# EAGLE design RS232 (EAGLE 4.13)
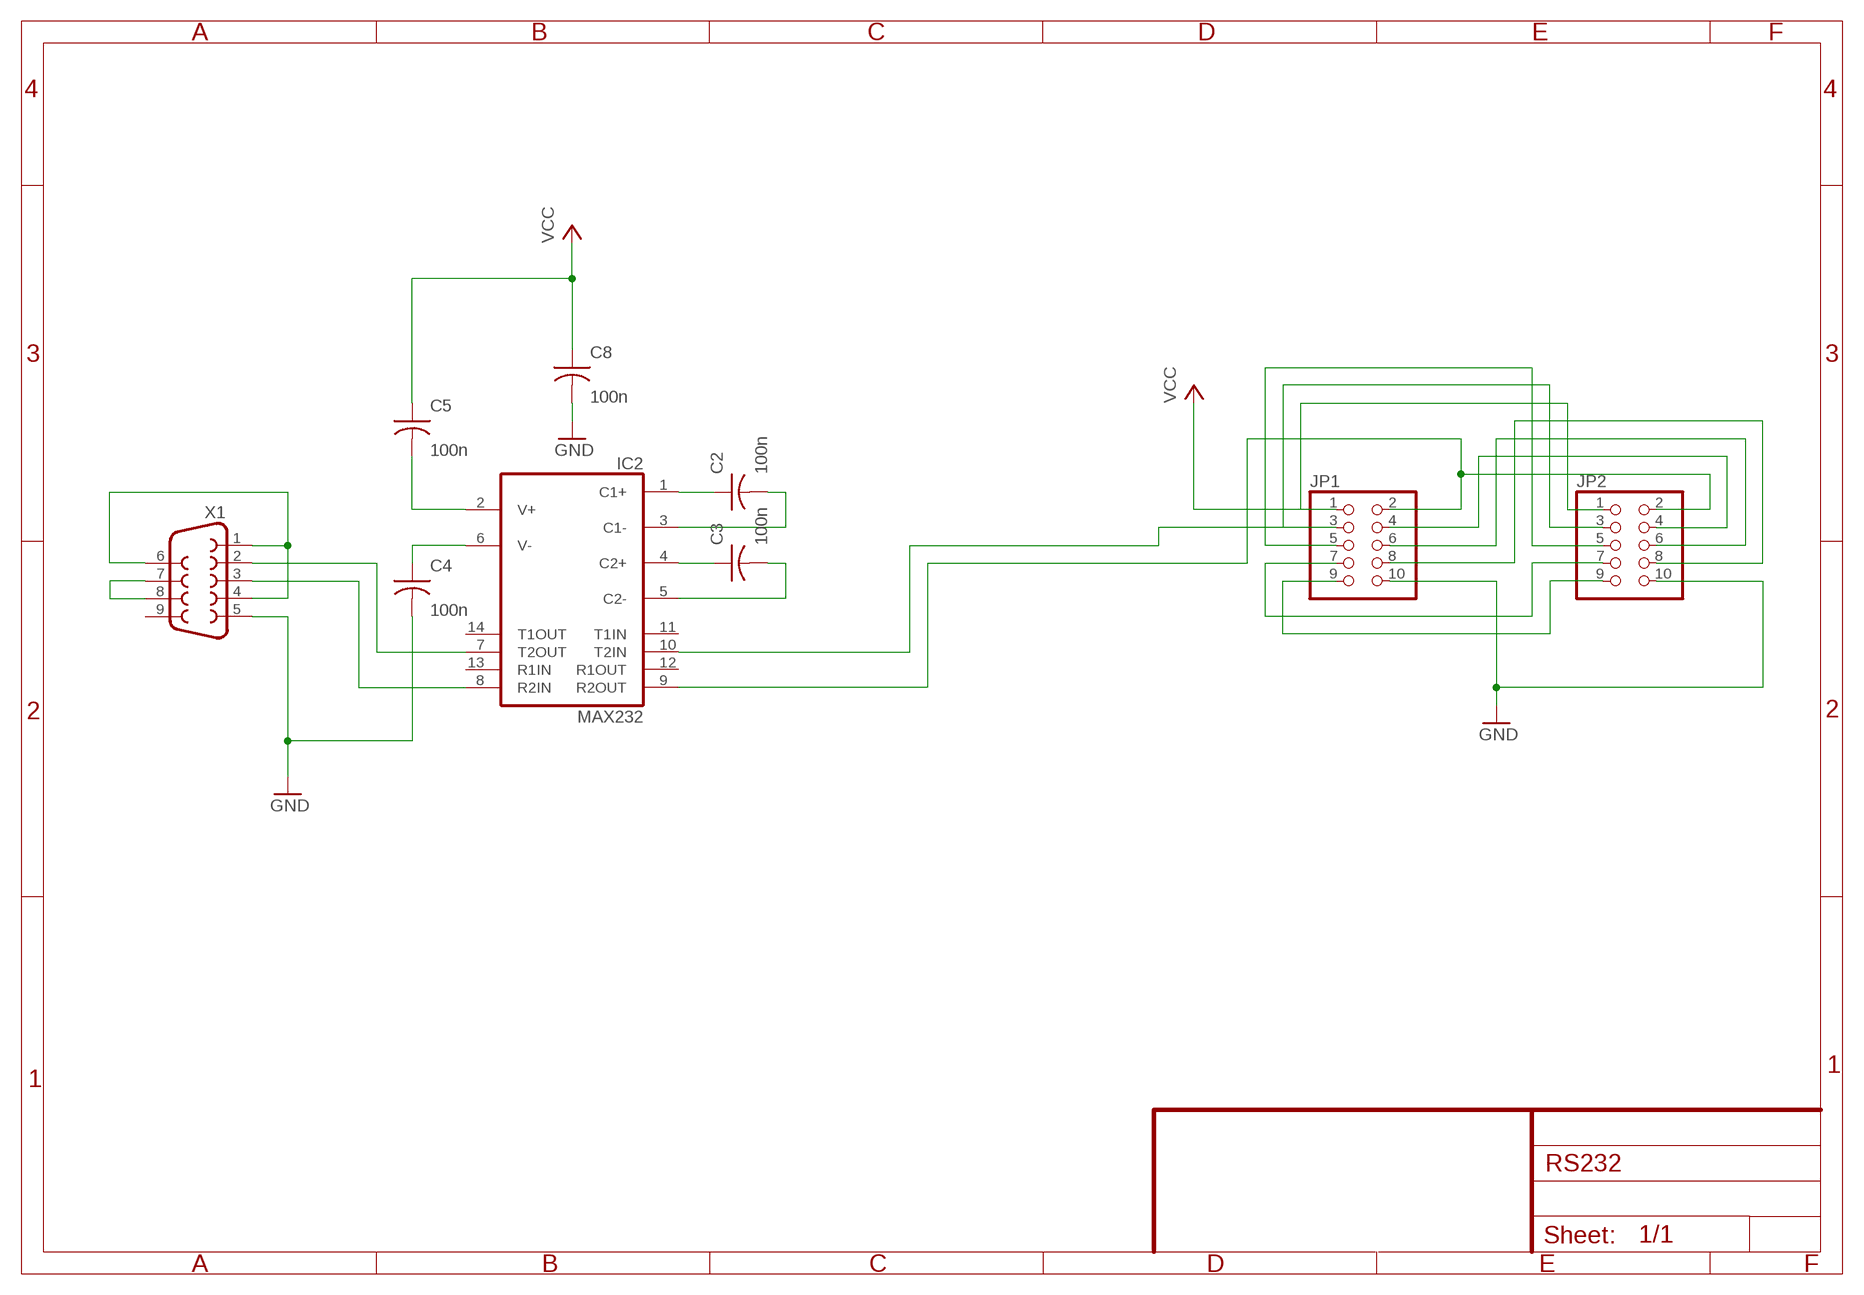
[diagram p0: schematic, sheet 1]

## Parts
C2  100n  CAP-2,5  [C-2,5]
C3  100n  CAP-2,5  [C-2,5]
C4  100n  CAP-2,5  [C-2,5]
C5  100n  CAP-2,5  [C-2,5]
C8  100n  CAP-2,5  [C-2,5]
IC2  MAX232  [DIL16]
JP1  PINHD-2X5  [2X05]
JP2  PINHD-2X5  [2X05]
X1  F09HP  [F09HP]

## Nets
GND: C4.2 C8.2 JP1.10 JP2.10 X1.5
N$1: X1.7 X1.8
N$2: X1.1 X1.4 X1.6
N$3: JP1.4 JP2.4
N$4: IC2.7(T2OUT) X1.2
N$5: JP1.6 JP2.6
N$6: IC2.8(R2IN) X1.3
N$7: JP1.8 JP2.8
N$10: IC2.10(T2IN) JP1.3 JP2.3
N$11: C4.1 IC2.6(V-)
N$12: IC2.9(R2OUT) JP1.2 JP2.2
N$13: JP1.5 JP2.5
N$14: JP1.7 JP2.7
N$15: JP1.9 JP2.9
N$21: C2.1 IC2.1(C1+)
N$22: C2.2 IC2.3(C1-)
N$23: C5.2 IC2.2(V+)
N$24: C3.1 IC2.4(C2+)
N$25: C3.2 IC2.5(C2-)
VCC: C5.1 C8.1 JP1.1 JP2.1
Unconnected: IC2.11(T1IN) IC2.12(R1OUT) IC2.13(R1IN) IC2.14(T1OUT) X1.9

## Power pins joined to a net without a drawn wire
GND: IC2.15(GND)
VCC: IC2.16(VCC)

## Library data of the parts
C2-C5 C8 = discrete:CAP-2,5
IC2 = maxim:MAX232: RS232 TRANSEIVER
JP1 JP2 = pinhead:PINHD-2X5: PIN HEADER
X1 = con-subd:F09: SUB-D

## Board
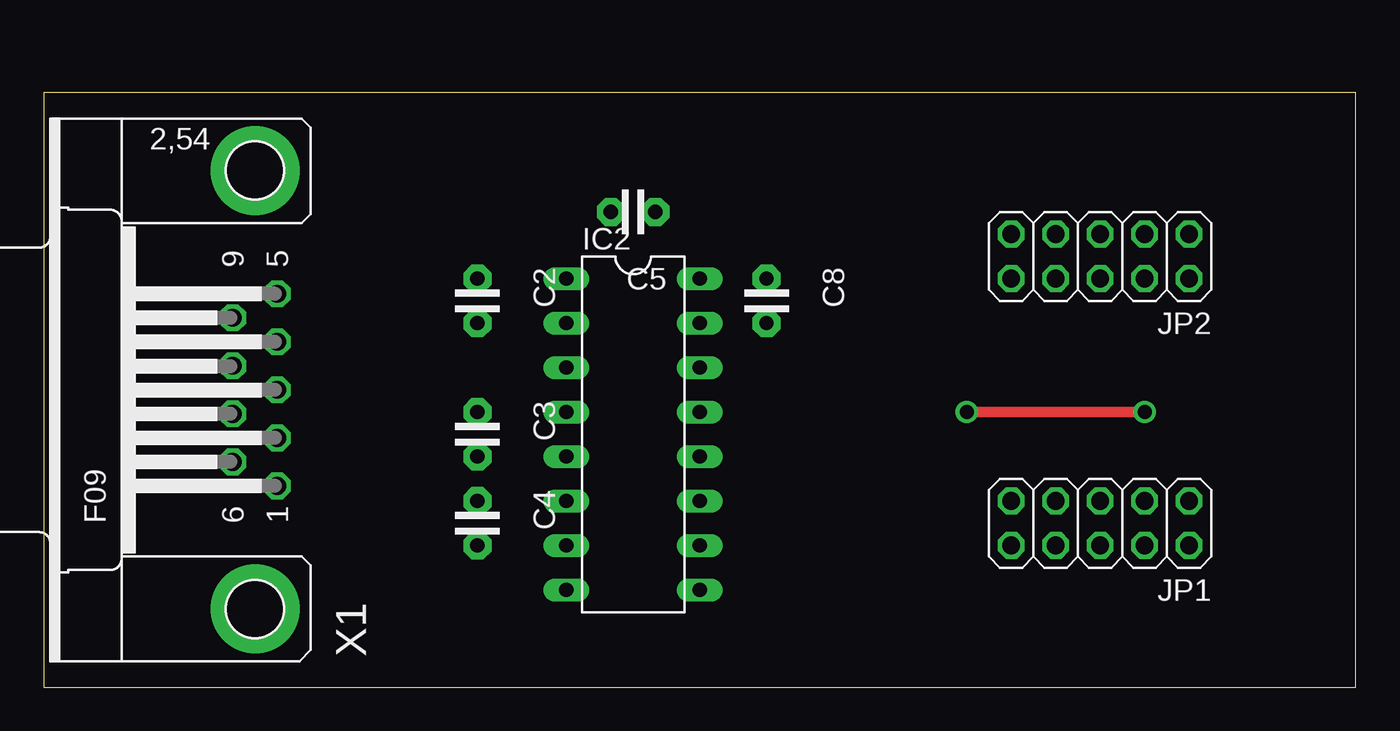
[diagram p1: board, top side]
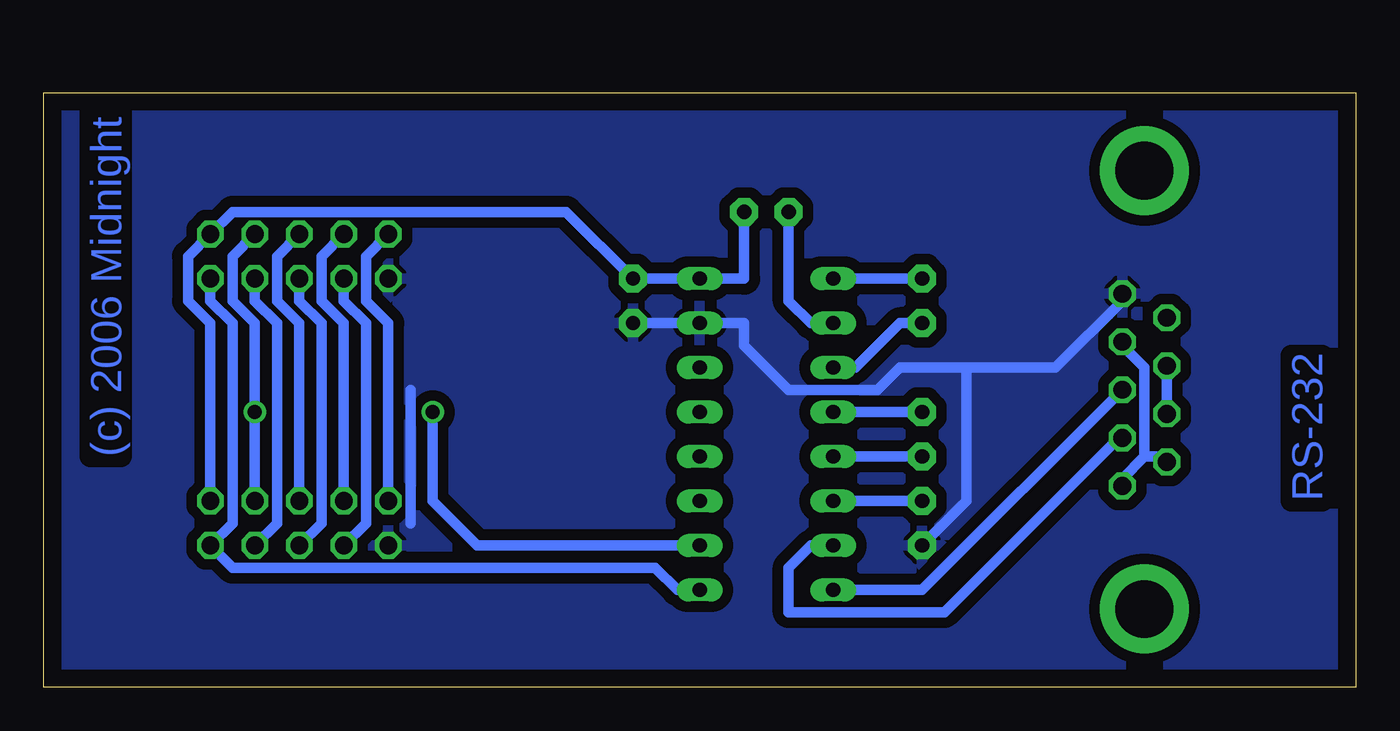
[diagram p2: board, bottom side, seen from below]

Size 74.91 x 33.96 mm. Coordinates in mm from the lower left corner, seen from the top.
Outline: 0,0 74.91,0 74.91,33.96 0,33.96 0,0
Copper layers (1*16): Top 0.035mm / dielectric 1.5mm / Bottom 0.035mm
Design rules "default": minimum track width 24mil, minimum drill 24mil, track to track 8mil, track to pad 8mil, pad to pad 8mil, via to via 8mil, smd to smd 8mil, copper to edge 40mil, drill to drill 8mil, minimum pad ring 10mil, minimum via ring 8mil, stop-mask expansion 4mil, vias tented up to drill 0mil, thermal gap 10mil

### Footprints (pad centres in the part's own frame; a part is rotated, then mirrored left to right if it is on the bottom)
C-2,5 = drill 0.813 pad 1.6 octagon: 1 -1.27,0; 2 1.27,0
DIL16 = drill 0.813 long: 1 -8.89,-3.81; 2 -6.35,-3.81; 3 -3.81,-3.81; 4 -1.27,-3.81; 5 1.27,-3.81; 6 3.81,-3.81; 7 6.35,-3.81; 8 8.89,-3.81; 9 8.89,3.81; 10 6.35,3.81; 11 3.81,3.81; 12 1.27,3.81; 13 -1.27,3.81; 14 -3.81,3.81; 15 -6.35,3.81; 16 -8.89,3.81
2X05 = drill 1.016 octagon: 1 -5.08,-1.27; 2 -5.08,1.27; 3 -2.54,-1.27; 4 -2.54,1.27; 5 0,-1.27; 6 0,1.27; 7 2.54,-1.27; 8 2.54,1.27; 9 5.08,-1.27; 10 5.08,1.27
F09HP = drill 1.016 octagon: 1 -5.486,-1.27; 2 -2.743,-1.27; 3 0,-1.27; 4 2.743,-1.27; 5 5.486,-1.27; 6 -4.115,1.27; 7 -1.372,1.27; 8 1.372,1.27; 9 4.115,1.27 | drill 3.302 pad 5.08 round: G1 -12.522,0; G2 12.522,0

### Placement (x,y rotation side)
C2  24.76,22.06 270 top
C3  24.76,14.44 270 top
C4  24.76,9.36 270 top
C5  33.65,27.14 180 top
C8  41.27,22.06 270 top
IC2  33.65,14.44 270 top
JP1  60.32,9.36 180 top
JP2  60.32,24.6 180 top
X1  12.06,16.98 90 top

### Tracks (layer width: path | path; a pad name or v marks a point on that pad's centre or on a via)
GND
  Bottom 0.61: C8.2 IC2.15 34.92,20.79 34.92,19.52 32.38,16.98 27.3,16.98 26.03,18.25 22.22,18.25 | 22.22,18.25 17.14,18.25 13.33,22.06 X1.5 | C4.2 22.22,10.63 22.22,18.25 | 53.97,9.36 53.97,16.98
  pour Bottom (isolate 0.61): 0.63,33.49 74.29,33.49 74.29,0.47 0.63,0.47
N$1
  Bottom 0.61: X1.7 X1.8
N$2
  Bottom 0.61: 12.06,13.17 13.33,11.9 X1.1 | 12.06,13.17 10.79,13.17 X1.6 | 12.06,13.17 12.06,18.25 13.33,19.52 X1.4
N$3
  Bottom 0.61: JP1.4 61.59,9.36 61.59,20.79 62.86,22.06 JP2.4
N$4
  Bottom 0.61: IC2.7 31.11,8.09 32.38,6.82 32.38,4.28 23.49,4.28 13.33,14.44 X1.2
N$5
  Bottom 0.61: JP1.6 59.05,9.36 59.05,20.79 60.32,22.06 JP2.6
N$6
  Bottom 0.61: X1.3 24.76,5.55 IC2.8
N$7
  Bottom 0.61: JP1.8 56.51,9.36 56.51,20.79 57.78,22.06 JP2.8
N$10  (via drill 0.8 pad 1.27)
  Top 0.61: v52.7,15.71 v62.86,15.71
  Bottom 0.61: JP2.3 64.13,24.6 64.13,22.06 62.86,20.79 v62.86,15.71 JP1.3 | v52.7,15.71 52.7,10.63 50.16,8.09 IC2.10
N$11
  Bottom 0.61: C4.1 IC2.6
N$12
  Bottom 0.61: JP2.2 65.4,22.06 64.13,20.79 64.13,9.36 JP1.2 64.13,6.82 40,6.82 38.73,5.55 IC2.9
N$13
  Bottom 0.61: JP1.5 60.32,20.79 61.59,22.06 61.59,24.6 JP2.5
N$14
  Bottom 0.61: JP1.7 57.78,20.79 59.05,22.06 59.05,24.6 JP2.7
N$15
  Bottom 0.61: JP1.9 55.24,20.79 56.51,22.06 56.51,24.6 JP2.9
N$21
  Bottom 0.61: C2.1 IC2.1
N$22
  Bottom 0.61: C2.2 26.03,20.79 28.57,18.25 IC2.3
N$23
  Bottom 0.61: C5.2 32.38,22.06 31.11,20.79 IC2.2
N$24
  Bottom 0.61: C3.1 IC2.4
N$25
  Bottom 0.61: C3.2 IC2.5
VCC
  Bottom 0.61: C5.1 34.92,23.33 IC2.16 C8.1 45.08,27.14 64.13,27.14 JP2.1 66.67,24.6 66.67,22.06 65.4,20.79 JP1.1

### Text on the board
Bottom: (c) 2006 Midnight | RS-232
